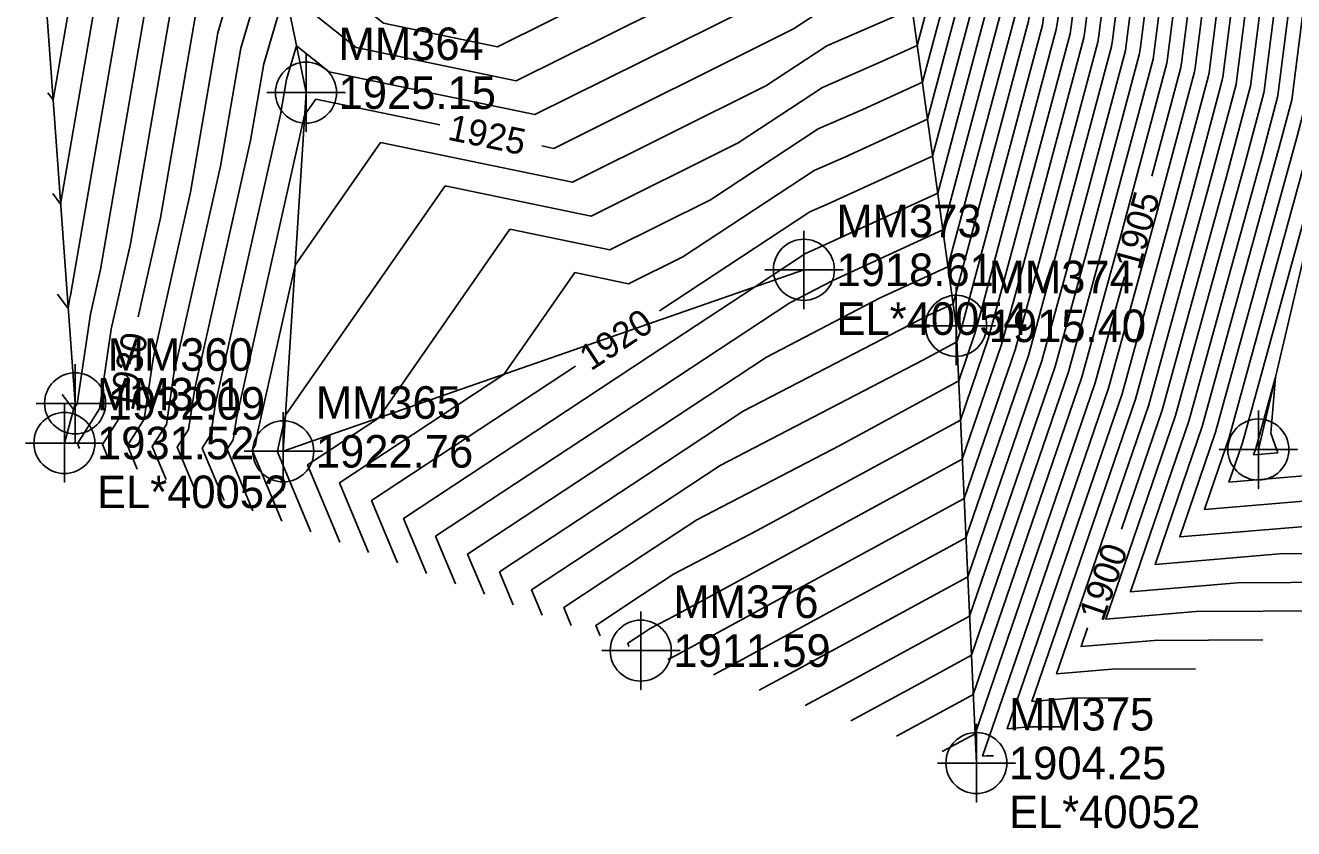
# Model space of a CAD drawing. Extents: x 1004378 to 1005103, y 553854 to 554288.
# Drawn here: x 1004893 to 1004990.4, y 553854.1 to 553915.8 of the extents above; entities that cross this region are included whole.
import ezdxf

# ---------------------------------------------------------------- set-up
doc = ezdxf.new("R2010")
doc.units = 0
for name, color, linetype in [('DTM Contours Major', 7, 'Continuous'), ('DTM Contours Major Text', 7, 'Continuous'), ('DTM Contours Minor', 7, 'Continuous'), ('Exist DTM Breakline', 7, 'Continuous'), ('Exist DTM Breakline Cogo Comment', 7, 'Continuous'), ('Exist DTM Breakline Cogo Elevation', 7, 'Continuous'), ('Exist DTM Breakline Cogo Number', 7, 'Continuous'), ('Exist DTM Breakline Cogo Point CELL', 7, 'Continuous'), ('Exist DTM Regular Point CELL', 7, 'Continuous'), ('Exist DTM Regular Point Cogo Elevation', 7, 'Continuous'), ('Exist DTM Regular Point Cogo Number', 7, 'Continuous')]:
    doc.layers.add(name, color=color, linetype=linetype)

msp = doc.modelspace()

# ---------------------------------------------------------------- linework, layer by layer
at = {"layer": 'DTM Contours Major'}
for points in [[(1004992.875, 554003.128), (1004992.418, 553993.617), (1004991.372, 553984.881), (1004990.915, 553980.071), (1004988.107, 553956.077), (1004986.932, 553951.455), (1004985.684, 553941.478), (1004984.331, 553932.757), (1004981.805, 553912.854), (1004981.751, 553912.525), (1004979.522, 553904.173)], [(1004971.479, 553987.875), (1004969.989, 553972.194), (1004969.198, 553965.438), (1004965.192, 553949.68), (1004964.904, 553947.376), (1004960.748, 553920.578), (1004960.368, 553920.099), (1004959.949, 553919.572), (1004959.874, 553919.536), (1004954.889, 553917.367), (1004952.025, 553915.484), (1004933.597, 553906.315), (1004932.685, 553906.503)], [(1004975.8, 553980.258), (1004975.22, 553974.163), (1004973.925, 553963.098), (1004970.627, 553950.123), (1004970.099, 553945.901), (1004966.549, 553923.013), (1004965.932, 553918.15), (1004965.808, 553917.384), (1004962.695, 553905.72), (1004954.669, 553902.046), (1004953.262, 553901.433), (1004941.713, 553893.841)], [(1004995.335, 553975.107), (1004992.834, 553953.737), (1004992.367, 553951.898), (1004990.879, 553940.003), (1004990.259, 553936.005), (1004987.096, 553911.089), (1004987.066, 553910.906), (1004985.268, 553904.169), (1004980.322, 553886.217), (1004977.192, 553877.08)], [(1004959.1, 553944.929), (1004959.013, 553944.368), (1004958.077, 553943.19), (1004951.417, 553933.392), (1004951.155, 553933.242), (1004929.405, 553920.793), (1004926.414, 553919.305), (1004924.709, 553919.658), (1004920.162, 553923.286), (1004912.286, 553929.547), (1004910.029, 553929.86), (1004909.966, 553929.387), (1004909.292, 553927.413), (1004906.06, 553916.388), (1004903.403, 553900.976), (1004901.694, 553893.379)], [(1004980.362, 553942.139), (1004978.404, 553929.509), (1004976.514, 553914.62), (1004976.437, 553914.145), (1004971.786, 553896.718), (1004970.051, 553890.42), (1004965.256, 553876.423), (1004947.497, 553866.765), (1004945.875, 553865.882)], [(1004900.883, 553933.338), (1004898.134, 553925.288), (1004897.276, 553922.361), (1004895.153, 553910.049), (1004894.759, 553910.571)], [(1004973.351, 553931.899), (1004972.477, 553926.261), (1004971.223, 553916.385), (1004971.123, 553915.765), (1004965.045, 553892.992), (1004964.916, 553892.521), (1004964.557, 553891.474), (1004961.933, 553890.047), (1004946.37, 553881.961), (1004940.591, 553878.151), (1004931.906, 553872.425), (1004932.715, 553870.481)], [(1004998.723, 553897.593), (1004999.243, 553904.133), (1004997.095, 553908.235), (1004995.526, 553920.31), (1004994.715, 553927.665), (1004992.386, 553909.324), (1004992.38, 553909.286), (1004992.009, 553907.895), (1004985.458, 553884.116), (1004984.06, 553880.034), (1004983.562, 553878.582), (1004995.745, 553879.603), (1005002.271, 553879.637)], [(1004924.851, 553908.123), (1004915.328, 553910.093), (1004914.469, 553908.86), (1004909.239, 553885.607), (1004908.992, 553883.94), (1004908.531, 553883.219), (1004910.504, 553878.48)], [(1004977.427, 553896.452), (1004975.187, 553888.318), (1004967.412, 553865.626), (1004965.954, 553861.371), (1004963.433, 553860)], [(1004935.269, 553889.597), (1004919.613, 553879.275), (1004921.609, 553874.481)], [(1004900.198, 553885.556), (1004898.938, 553883.583), (1004899.398, 553882.48)], [(1004974.599, 553869.512), (1004974.103, 553868.065), (1004979.703, 553868.534), (1004988.062, 553868.578)]]:
    msp.add_lwpolyline(points, dxfattribs=at)
at = {"layer": 'DTM Contours Minor'}
for points in [[(1004972.981, 554045.52), (1004972.185, 554009.926), (1004971.721, 554000.256), (1004971.362, 553997.261), (1004968.942, 553971.8), (1004968.253, 553965.906), (1004964.105, 553949.591), (1004963.865, 553947.671), (1004960.401, 553925.336), (1004957.491, 553921.673), (1004957.35, 553921.495), (1004957.063, 553921.358), (1004955.215, 553920.554), (1004954.153, 553919.855), (1004932.16, 553908.913), (1004916.353, 553912.182), (1004913.842, 553914.186), (1004913.087, 553911.609), (1004912.621, 553908.909), (1004907.637, 553886.746), (1004907.279, 553884.335), (1004906.612, 553883.292), (1004908.282, 553879.28)], [(1004975.015, 554045.638), (1004974.241, 554011.059), (1004973.692, 553999.624), (1004973.268, 553996.082), (1004971.035, 553972.588), (1004970.143, 553964.97), (1004966.279, 553949.768), (1004965.943, 553947.081), (1004961.807, 553920.414), (1004961.699, 553919.562), (1004961.557, 553918.68), (1004961.124, 553917.06), (1004960.01, 553916.55), (1004954.564, 553914.18), (1004949.897, 553911.112), (1004935.034, 553903.717), (1004920.298, 553906.764), (1004913.738, 553897.346), (1004910.842, 553884.469), (1004910.705, 553883.545), (1004910.449, 553883.146), (1004912.725, 553877.68)], [(1004976.003, 554044.458), (1004975.269, 554011.625), (1004974.678, 553999.308), (1004974.221, 553995.492), (1004972.081, 553972.981), (1004971.089, 553964.502), (1004967.366, 553949.857), (1004966.982, 553946.786), (1004962.993, 553921.064), (1004962.757, 553919.209), (1004962.62, 553918.356), (1004961.517, 553914.225), (1004958.675, 553912.924), (1004954.239, 553910.994), (1004947.768, 553906.74), (1004936.47, 553901.118), (1004925.269, 553903.435), (1004913.007, 553885.833), (1004912.444, 553883.33), (1004912.418, 553883.151), (1004912.368, 553883.073), (1004914.946, 553876.88)], [(1004976.992, 554043.278), (1004976.297, 554012.192), (1004975.663, 553998.992), (1004975.174, 553994.903), (1004973.128, 553973.375), (1004972.034, 553964.034), (1004968.453, 553949.946), (1004968.021, 553946.491), (1004964.178, 553921.714), (1004963.816, 553918.856), (1004963.683, 553918.032), (1004961.91, 553911.39), (1004957.339, 553909.298), (1004953.913, 553907.807), (1004945.64, 553902.368), (1004937.907, 553898.52), (1004930.24, 553900.106), (1004920.136, 553885.602), (1004914.696, 553882.016), (1004917.167, 553876.081)], [(1004971.881, 554041.705), (1004971.157, 554009.36), (1004970.735, 554000.573), (1004970.409, 553997.85), (1004967.896, 553971.406), (1004967.307, 553966.374), (1004963.018, 553949.502), (1004962.826, 553947.966), (1004960.054, 553930.094), (1004956.322, 553925.395), (1004955.382, 553924.012), (1004954.895, 553923.733), (1004952.275, 553922.234), (1004930.724, 553911.511), (1004918.442, 553914.051), (1004912.975, 553918.414), (1004911.33, 553912.804), (1004910.317, 553906.926), (1004906.034, 553887.884), (1004905.566, 553884.73), (1004904.694, 553883.365), (1004906.061, 553880.08)], [(1004977.981, 554042.098), (1004977.325, 554012.758), (1004976.649, 553998.676), (1004976.126, 553994.313), (1004974.174, 553973.769), (1004972.98, 553963.566), (1004969.54, 553950.035), (1004969.06, 553946.196), (1004965.364, 553922.363), (1004964.874, 553918.503), (1004964.745, 553917.708), (1004962.303, 553908.555), (1004956.004, 553905.672), (1004953.588, 553904.62), (1004943.512, 553897.997), (1004939.343, 553895.922), (1004935.21, 553896.777), (1004929.764, 553888.959), (1004917.155, 553880.646), (1004919.388, 553875.281)], [(1004979.959, 554039.738), (1004979.381, 554013.891), (1004978.62, 553998.043), (1004978.032, 553993.134), (1004976.267, 553974.557), (1004974.871, 553962.63), (1004971.714, 553950.212), (1004971.138, 553945.606), (1004967.735, 553923.663), (1004966.99, 553917.797), (1004966.871, 553917.06), (1004963.088, 553902.885), (1004953.334, 553898.42), (1004952.937, 553898.247), (1004949.019, 553895.671), (1004940.949, 553890.351), (1004922.072, 553877.905), (1004923.831, 553873.681)], [(1004980.948, 554038.558), (1004980.409, 554014.457), (1004979.606, 553997.727), (1004978.985, 553992.545), (1004977.313, 553974.951), (1004975.816, 553962.162), (1004972.801, 553950.301), (1004972.177, 553945.311), (1004968.92, 553924.312), (1004968.048, 553917.444), (1004967.934, 553916.736), (1004963.481, 553900.05), (1004955.023, 553896.178), (1004951.726, 553894.465), (1004940.859, 553887.301), (1004924.53, 553876.535), (1004926.052, 553872.881)], [(1004988.333, 554039.04), (1004987.87, 554030.298), (1004987.604, 554018.421), (1004986.505, 553995.514), (1004985.655, 553988.418), (1004984.637, 553977.708), (1004982.434, 553958.886), (1004980.41, 553950.922), (1004979.45, 553943.247), (1004977.219, 553928.86), (1004975.456, 553914.973), (1004975.374, 553914.469), (1004970.438, 553895.973), (1004969.024, 553890.84), (1004965.116, 553879.433), (1004942.966, 553867.387), (1004942.363, 553867.059)], [(1004970.78, 554037.89), (1004970.129, 554008.794), (1004969.75, 554000.889), (1004969.456, 553998.44), (1004966.85, 553971.012), (1004966.362, 553966.842), (1004961.931, 553949.413), (1004961.787, 553948.261), (1004959.707, 553934.852), (1004956.907, 553931.326), (1004954.06, 553927.139), (1004953.648, 553926.903), (1004944.652, 553921.754), (1004929.287, 553914.109), (1004920.531, 553915.92), (1004912.107, 553922.642), (1004909.573, 553913.998), (1004908.012, 553904.943), (1004904.431, 553889.023), (1004903.852, 553885.125), (1004902.775, 553883.437), (1004903.84, 553880.88)], [(1004981.937, 554037.378), (1004981.437, 554015.023), (1004980.591, 553997.411), (1004979.938, 553991.955), (1004978.359, 553975.345), (1004976.762, 553961.694), (1004973.888, 553950.39), (1004973.216, 553945.017), (1004970.106, 553924.962), (1004969.106, 553917.091), (1004968.997, 553916.413), (1004963.874, 553897.215), (1004958.674, 553894.835), (1004949.941, 553890.297), (1004940.77, 553884.251), (1004926.989, 553875.165), (1004928.273, 553872.081)], [(1004990.374, 554037.886), (1004989.848, 554027.938), (1004989.66, 554019.554), (1004988.476, 553994.882), (1004987.561, 553987.239), (1004986.73, 553978.495), (1004984.325, 553957.95), (1004982.584, 553951.1), (1004981.528, 553942.657), (1004979.589, 553930.159), (1004977.572, 553914.267), (1004977.5, 553913.821), (1004973.135, 553897.463), (1004971.078, 553890), (1004965.395, 553873.413), (1004952.028, 553866.143), (1004949.387, 553864.706)], [(1004991.395, 554037.308), (1004990.837, 554026.758), (1004990.688, 554020.12), (1004989.461, 553994.565), (1004988.514, 553986.649), (1004987.776, 553978.889), (1004985.27, 553957.481), (1004983.671, 553951.188), (1004982.567, 553942.362), (1004980.775, 553930.808), (1004978.63, 553913.914), (1004978.563, 553913.497), (1004974.483, 553898.208), (1004972.105, 553889.579), (1004965.535, 553870.402), (1004956.559, 553865.52), (1004952.898, 553863.53)], [(1004992.416, 554036.731), (1004991.826, 554025.578), (1004991.716, 554020.686), (1004990.447, 553994.249), (1004989.467, 553986.06), (1004988.823, 553979.283), (1004986.216, 553957.013), (1004984.758, 553951.277), (1004983.606, 553942.067), (1004981.96, 553931.458), (1004979.688, 553913.561), (1004979.626, 553913.173), (1004975.831, 553898.953), (1004973.133, 553889.159), (1004965.675, 553867.392), (1004961.09, 553864.898), (1004956.41, 553862.353)], [(1004982.926, 554036.198), (1004982.465, 554015.589), (1004981.577, 553997.095), (1004980.891, 553991.365), (1004979.406, 553975.738), (1004977.707, 553961.226), (1004974.975, 553950.478), (1004974.255, 553944.722), (1004971.291, 553925.611), (1004970.165, 553916.738), (1004970.06, 553916.089), (1004964.266, 553894.38), (1004962.325, 553893.491), (1004948.155, 553886.129), (1004940.68, 553881.201), (1004929.448, 553873.795), (1004930.494, 553871.281)], [(1004993.436, 554036.154), (1004992.815, 554024.398), (1004992.744, 554021.253), (1004991.433, 553993.933), (1004990.419, 553985.47), (1004989.869, 553979.677), (1004987.161, 553956.545), (1004985.845, 553951.366), (1004984.645, 553941.773), (1004983.146, 553932.108), (1004980.746, 553913.208), (1004980.689, 553912.849), (1004977.179, 553899.699), (1004974.16, 553888.739), (1004965.815, 553864.382), (1004965.62, 553864.276), (1004959.921, 553861.177)], [(1004962.103, 554035.124), (1004964.176, 554015.003), (1004963.961, 554005.396), (1004963.836, 554002.786), (1004963.739, 554001.977), (1004961.543, 553978.867), (1004960.365, 553971.573), (1004959.55, 553968.659), (1004959.529, 553968.584), (1004954.54, 553953.078), (1004946.569, 553945.413), (1004946.073, 553945.13), (1004931.594, 553941.701), (1004919.839, 553937.548), (1004918.483, 553938.626), (1004904.825, 553940.523), (1004904.444, 553937.659), (1004900.366, 553925.713), (1004899.032, 553921.166), (1004895.735, 553902.041), (1004895.123, 553902.853)], [(1004969.679, 554034.076), (1004969.101, 554008.227), (1004968.764, 554001.205), (1004968.504, 553999.029), (1004965.804, 553970.618), (1004965.416, 553967.31), (1004960.844, 553949.324), (1004960.748, 553948.556), (1004959.36, 553939.61), (1004957.492, 553937.258), (1004952.739, 553930.265), (1004952.402, 553930.072), (1004937.029, 553921.274), (1004927.851, 553916.707), (1004922.62, 553917.789), (1004911.24, 553926.87), (1004907.816, 553915.193), (1004905.707, 553902.959), (1004902.829, 553890.161), (1004902.139, 553885.52), (1004900.857, 553883.51), (1004901.619, 553881.68)], [(1004984.903, 554033.838), (1004984.52, 554016.722), (1004983.548, 553996.462), (1004982.797, 553990.186), (1004981.498, 553976.526), (1004979.598, 553960.29), (1004977.149, 553950.656), (1004976.333, 553944.132), (1004973.662, 553926.911), (1004972.281, 553916.032), (1004972.186, 553915.441), (1004966.394, 553893.738), (1004965.943, 553892.101), (1004964.697, 553888.464), (1004955.582, 553883.507), (1004944.585, 553877.793), (1004940.501, 553875.1), (1004934.365, 553871.055), (1004934.936, 553869.681)], [(1004985.892, 554032.658), (1004985.548, 554017.288), (1004984.533, 553996.146), (1004983.749, 553989.597), (1004982.545, 553976.92), (1004980.543, 553959.822), (1004978.236, 553950.745), (1004977.372, 553943.837), (1004974.848, 553927.56), (1004973.339, 553915.679), (1004973.248, 553915.117), (1004967.742, 553894.483), (1004966.97, 553891.681), (1004964.836, 553885.454), (1004949.23, 553876.966), (1004942.8, 553873.625), (1004940.412, 553872.05), (1004936.823, 553869.685), (1004937.157, 553868.881)], [(1004986.881, 554031.478), (1004986.576, 554017.855), (1004985.519, 553995.83), (1004984.702, 553989.007), (1004983.591, 553977.314), (1004981.489, 553959.354), (1004979.323, 553950.833), (1004978.411, 553943.542), (1004976.033, 553928.21), (1004974.397, 553915.326), (1004974.311, 553914.793), (1004969.09, 553895.228), (1004967.997, 553891.26), (1004964.976, 553882.444), (1004942.879, 553870.426), (1004941.014, 553869.457), (1004940.322, 553869), (1004939.282, 553868.314), (1004939.379, 553868.082)], [(1004993.008, 553980.858), (1004989.998, 553955.141), (1004989.106, 553951.632), (1004987.762, 553940.888), (1004986.702, 553934.057), (1004983.921, 553912.148), (1004983.877, 553911.878), (1004981.224, 553901.934), (1004977.241, 553887.478), (1004970.741, 553868.507), (1004968.428, 553861.755), (1004970.077, 553861.893), (1004972.539, 553861.906)], [(1004991.962, 553980.464), (1004989.052, 553955.609), (1004988.019, 553951.543), (1004986.723, 553941.183), (1004985.517, 553933.407), (1004982.863, 553912.501), (1004982.814, 553912.201), (1004979.875, 553901.189), (1004976.214, 553887.898), (1004969.077, 553867.067), (1004966.536, 553859.651), (1004966.868, 553859.679), (1004967.364, 553859.682)], [(1004990.943, 553954.673), (1004990.193, 553951.721), (1004988.801, 553940.593), (1004987.888, 553934.706), (1004984.979, 553911.795), (1004984.94, 553911.554), (1004982.572, 553902.679), (1004978.268, 553887.058), (1004972.406, 553869.948), (1004970.32, 553863.858), (1004973.285, 553864.107), (1004977.713, 553864.13)], [(1004991.28, 553951.81), (1004989.84, 553940.298), (1004989.073, 553935.356), (1004986.037, 553911.442), (1004986.003, 553911.23), (1004983.92, 553903.424), (1004979.295, 553886.637), (1004974.071, 553871.389), (1004972.211, 553865.961), (1004976.494, 553866.321), (1004982.888, 553866.354)], [(1005014.217, 553877.325), (1005014.091, 553877.592), (1005013.704, 553878.533), (1005012.857, 553880.816), (1005011.63, 553883.712), (1005008.291, 553893.385), (1005005.055, 553901.35), (1005002.81, 553906.873), (1005001.107, 553914.274), (1004997.761, 553922.328), (1004996.88, 553929.106), (1004995.829, 553938.637), (1004995.652, 553940.134), (1004995.446, 553942.113), (1004995.035, 553938.823), (1004995.001, 553938.604), (1004991.328, 553909.677), (1004991.317, 553909.61), (1004990.661, 553907.15), (1004984.431, 553884.536), (1004982.395, 553878.594), (1004981.67, 553876.478), (1004992.537, 553877.39), (1005008.76, 553877.474)], [(1004993.815, 553937.954), (1004990.27, 553910.03), (1004990.255, 553909.934), (1004989.313, 553906.405), (1004983.404, 553884.956), (1004980.73, 553877.153), (1004979.778, 553874.375), (1004989.328, 553875.176), (1005003.585, 553875.25)], [(1004992.63, 553937.305), (1004989.212, 553910.383), (1004989.192, 553910.258), (1004987.965, 553905.66), (1004982.377, 553885.376), (1004979.065, 553875.712), (1004977.887, 553872.272), (1004986.12, 553872.962), (1004998.411, 553873.026)], [(1004991.444, 553936.655), (1004988.154, 553910.736), (1004988.129, 553910.582), (1004986.616, 553904.915), (1004981.349, 553885.797), (1004977.401, 553874.271), (1004975.995, 553870.168), (1004982.911, 553870.748), (1004993.236, 553870.802)], [(1004900.789, 553919.972), (1004896.488, 553895.026), (1004896.419, 553894.715), (1004896.317, 553894.032), (1004896.245, 553894.129), (1004895.487, 553895.134)], [(1004902.546, 553918.777), (1004898.793, 553897.009), (1004898.021, 553893.577), (1004897, 553886.704), (1004896.719, 553886.263), (1004896.097, 553887.088), (1004895.851, 553887.415)], [(1004904.303, 553917.582), (1004901.098, 553898.992), (1004899.624, 553892.438), (1004898.713, 553886.309), (1004897.02, 553883.656), (1004897.177, 553883.28)], [(1004996.933, 553881.648), (1004996.51, 553882.869), (1004993.701, 553891.026), (1004995.032, 553907.769), (1004994.535, 553908.719), (1004994.171, 553911.514), (1004993.984, 553913.216), (1004993.445, 553908.971), (1004993.443, 553908.962), (1004993.357, 553908.64), (1004986.485, 553883.695), (1004985.724, 553881.475), (1004985.454, 553880.685), (1004996.933, 553881.648)], [(1004989.019, 553888.745), (1004987.512, 553883.275), (1004987.389, 553882.916), (1004987.345, 553882.788), (1004989.201, 553882.944), (1004989.133, 553883.141), (1004988.678, 553884.46), (1004989.019, 553888.745)]]:
    msp.add_lwpolyline(points, dxfattribs=at)
at = {"layer": 'Exist DTM Breakline'}
for points in [[(1004987.71, 553883.194), (1004993.763, 553908.865), (1004995.956, 553952.192), (1004996.06, 553992.449), (1004993.928, 554035.876), (1004994.309, 554070.389), (1004993.033, 554080.737), (1004990.275, 554106.198), (1004991.435, 554130.882), (1004994.664, 554165.005), (1004997.714, 554181.706), (1005005.106, 554206.988)], [(1004908.599, 554113.626), (1004928.542, 554104.358), (1004950.697, 554094.299), (1004945.541, 554080.331), (1004948.745, 554053.974), (1004946.395, 554048.586), (1004946.774, 554014.511), (1004946.946, 553994.845), (1004942.426, 553964.624), (1004933.56, 553959.38), (1004919.92, 553960.138), (1004910.869, 553961.543), (1004894.885, 553951.978), (1004894.101, 553924.52), (1004896.848, 553886.739), (1004896.026, 553883.694)], [(1004961.787, 553969.107), (1004958.665, 553949.147), (1004960.871, 553918.889), (1004964.5, 553892.691), (1004966.059, 553859.121)], [(1004898.767, 553952.935), (1004911.06, 553927.75), (1004914.579, 553910.594), (1004912.831, 553883.055), (1004952.809, 553896.992)]]:
    msp.add_lwpolyline(points, dxfattribs=at)
at = {"layer": 'Exist DTM Breakline Cogo Point CELL'}
for points in [[(1004914.579, 553913.594), (1004914.579, 553907.594), (1004914.579, 553910.594), (1004917.579, 553910.594), (1004911.579, 553910.594)], [(1004952.809, 553899.992), (1004952.809, 553893.992), (1004952.809, 553896.992), (1004955.809, 553896.992), (1004949.809, 553896.992)], [(1004964.5, 553895.691), (1004964.5, 553889.691), (1004964.5, 553892.691), (1004967.5, 553892.691), (1004961.5, 553892.691)], [(1004896.848, 553889.739), (1004896.848, 553883.739), (1004896.848, 553886.739), (1004899.848, 553886.739), (1004893.848, 553886.739)], [(1004896.026, 553886.694), (1004896.026, 553880.694), (1004896.026, 553883.694), (1004899.026, 553883.694), (1004893.026, 553883.694)], [(1004912.831, 553886.055), (1004912.831, 553880.055), (1004912.831, 553883.055), (1004915.831, 553883.055), (1004909.831, 553883.055)], [(1004987.71, 553886.194), (1004987.71, 553880.194), (1004987.71, 553883.194), (1004990.71, 553883.194), (1004984.71, 553883.194)], [(1004966.059, 553862.121), (1004966.059, 553856.121), (1004966.059, 553859.121), (1004969.059, 553859.121), (1004963.059, 553859.121)]]:
    msp.add_lwpolyline(points, dxfattribs=at)
for centre in [(1004914.579, 553910.594), (1004952.809, 553896.992), (1004964.5, 553892.691), (1004896.848, 553886.739), (1004896.026, 553883.694), (1004912.831, 553883.055), (1004987.71, 553883.194), (1004966.059, 553859.121)]:
    msp.add_circle(centre, 2.344, dxfattribs=at)
at = {"layer": 'Exist DTM Regular Point CELL'}
msp.add_lwpolyline([(1004940.285, 553870.755), (1004940.285, 553864.755), (1004940.285, 553867.755), (1004943.285, 553867.755), (1004937.285, 553867.755)], dxfattribs=at)
msp.add_circle((1004940.285, 553867.755), 2.344, dxfattribs=at)

# ---------------------------------------------------------------- texts
at = {"layer": 'DTM Contours Major Text'}
for s, rotation, p in [('1925', 348.31562, (1004925.381, 553906.993)), ('1905', 74.81949, (1004978.603, 553896.908)), ('1920', 33.36894, (1004936.442, 553889.175)), ('1930', 79.17347, (1004901.329, 553886.1)), ('1900', 71.08748, (1004975.788, 553869.896))]:
    msp.add_text(s, height=2, rotation=rotation, dxfattribs=at).set_placement(p)
at = {"layer": 'Exist DTM Breakline Cogo Comment'}
for s, p in [('EL*40054', (1004955.309, 553891.992)), ('EL*40052', (1004898.526, 553878.694)), ('EL*40052', (1004968.559, 553854.121))]:
    msp.add_text(s, height=2.5, dxfattribs=at).set_placement(p)
at = {"layer": 'Exist DTM Breakline Cogo Elevation'}
for s, p in [('1925.15', (1004917.079, 553909.344)), ('1918.61', (1004955.309, 553895.742)), ('1915.40', (1004967, 553891.441)), ('1932.09', (1004899.348, 553885.489)), ('1931.52', (1004898.526, 553882.444)), ('1922.76', (1004915.331, 553881.805)), ('1904.25', (1004968.559, 553857.871))]:
    msp.add_text(s, height=2.5, dxfattribs=at).set_placement(p)
at = {"layer": 'Exist DTM Breakline Cogo Number'}
for s, p in [('MM364', (1004917.079, 553913.094)), ('MM373', (1004955.309, 553899.492)), ('MM374', (1004967, 553895.191)), ('MM360', (1004899.348, 553889.239)), ('MM361', (1004898.526, 553886.194)), ('MM365', (1004915.331, 553885.555)), ('MM375', (1004968.559, 553861.621))]:
    msp.add_text(s, height=2.5, dxfattribs=at).set_placement(p)
at = {"layer": 'Exist DTM Regular Point Cogo Elevation'}
msp.add_text('1911.59', height=2.5, dxfattribs=at).set_placement((1004942.785, 553866.505))
at = {"layer": 'Exist DTM Regular Point Cogo Number'}
msp.add_text('MM376', height=2.5, dxfattribs=at).set_placement((1004942.785, 553870.255))

doc.saveas('drawing.dxf')
